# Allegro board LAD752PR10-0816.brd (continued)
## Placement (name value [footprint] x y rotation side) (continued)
CG220  1U_0402_6.3V4Z  [C_0402]  253.82 134.09 270 top
CG221  1U_0402_6.3V4Z  [C_0402]  250.82 134.12 270 top
CG222  1U_0402_6.3V6K  [C_0402]  265.79 102.86 0 bottom
CG223  1U_0402_6.3V6K  [C_0402]  265.85 125.47 0 bottom
CG224  1U_0402_6.3V6K  [C_0402]  266.7 105.53 180 bottom
CG225  1U_0402_6.3V6K  [C_0402]  266.76 122.74 180 bottom
CG226  1U_0402_6.3V6K  [C_0402]  272.59 129.16 270 bottom
CG227  1U_0402_6.3V6K  [C_0402]  277.44 100.95 270 top
CG228  1U_0402_6.3V6K  [C_0402]  275.39 128.25 90 bottom
CG229  1U_0402_6.3V6K  [C_0402]  276.54 100.9 180 top
CG230  10U_0603_6.3V6M  [C_0603]  281.76 114.9 270 top
CG231  1U_0402_6.3V4Z  [C_0402]  276.61 127.24 270 top
CG232  1U_0402_6.3V4Z  [C_0402]  271.58 128.25 90 bottom
CG233  1U_0402_6.3V4Z  [C_0402]  270.56 128.25 90 bottom
CG234  1U_0402_6.3V4Z  [C_0402]  283.84 119.35 0 bottom
CG235  0.1U_0402_10V6K  [C_0402]  283.84 120.81 0 bottom
CG236  0.1U_0402_10V6K  [C_0402]  279.79 115.04 270 top
CG237  0.1U_0402_10V6K  [C_0402]  284.02 124.51 90 bottom
CG238  0.1U_0402_10V6K  [C_0402]  280.36 126.32 90 top
CG239  0.1U_0402_10V6K  [C_0402]  277.75 114.14 0 top
CG240  0.1U_0402_10V6K  [C_0402]  277.75 115.03 0 top
CG241  0.1U_0402_10V6K  [C_0402]  283.84 117.76 0 bottom
CG242  0.1U_0402_10V6K  [C_0402]  277.59 126.39 0 top
CG243  1U_0402_6.3V4Z  [C_0402]  276.61 115.04 270 top
CG244  1U_0402_6.3V4Z  [C_0402]  280.68 115.04 270 top
CG245  1U_0402_6.3V4Z  [C_0402]  281.76 126.32 90 top
CG246  1U_0402_6.3V4Z  [C_0402]  283.84 102.08 0 bottom
CG247  10U_0603_6.3V6M  [C_0603]  281.89 107.16 180 top
CG248  1U_0402_6.3V4Z  [C_0402]  265.78 101.86 0 bottom
CG249  1U_0402_6.3V4Z  [C_0402]  281.11 112.24 0 top
CG250  1U_0402_6.3V4Z  [C_0402]  279.54 107.11 270 top
CG251  1U_0402_6.3V4Z  [C_0402]  283.84 104.62 0 bottom
CG252  0.1U_0402_10V6K  [C_0402]  281.57 101.07 270 top
CG253  0.1U_0402_10V6K  [C_0402]  280.64 105.72 0 top
CG254  0.1U_0402_10V6K  [C_0402]  279.78 105.02 180 top
CG255  0.1U_0402_10V6K  [C_0402]  277.3 109.82 0 top
CG256  0.1U_0402_10V6K  [C_0402]  283.84 101.12 0 bottom
CG257  0.1U_0402_10V6K  [C_0402]  277.41 112.77 0 top
CG258  0.1U_0402_10V6K  [C_0402]  283.84 103.35 0 bottom
CG259  0.1U_0402_10V6K  [C_0402]  279.33 112.24 0 top
CG260  1U_0402_6.3V4Z  [C_0402]  283.84 109.82 0 bottom
CG261  1U_0402_6.3V4Z  [C_0402]  277.3 103.35 0 top
CG262  1U_0402_6.3V4Z  [C_0402]  279.76 101.15 0 top
CG263  1U_0402_6.3V4Z  [C_0402]  279.78 108.32 180 top
CG264  1U_0402_6.3V6K  [C_0402]  265.79 91.94 0 bottom
CG265  1U_0402_6.3V6K  [C_0402]  265.79 74.82 0 bottom
CG266  1U_0402_6.3V6K  [C_0402]  266.7 94.61 180 bottom
CG267  1U_0402_6.3V6K  [C_0402]  266.7 77.49 180 bottom
CG268  1U_0402_6.3V6K  [C_0402]  283.84 95.47 0 bottom
CG269  1U_0402_6.3V6K  [C_0402]  278.57 72.61 180 top
CG270  1U_0402_6.3V6K  [C_0402]  283.84 99.24 0 bottom
CG271  1U_0402_6.3V6K  [C_0402]  276.79 72.61 180 top
CG272  10U_0603_6.3V6M  [C_0603]  276.3 91.92 180 top
CG273  1U_0402_6.3V4Z  [C_0402]  283.84 89.44 0 bottom
CG274  1U_0402_6.3V4Z  [C_0402]  283.84 90.84 0 bottom
CG275  1U_0402_6.3V4Z  [C_0402]  279.21 98.2 0 top
CG276  1U_0402_6.3V4Z  [C_0402]  283.84 87.09 0 bottom
CG277  0.1U_0402_10V6K  [C_0402]  283.84 94.14 0 bottom
CG278  0.1U_0402_10V6K  [C_0402]  278.25 93.38 0 top
CG279  0.1U_0402_10V6K  [C_0402]  280.98 98.2 0 top
CG280  0.1U_0402_10V6K  [C_0402]  283.84 97.44 0 bottom
CG281  0.1U_0402_10V6K  [C_0402]  283.84 91.73 0 bottom
CG282  0.1U_0402_10V6K  [C_0402]  278.15 91.85 180 top
CG283  0.1U_0402_10V6K  [C_0402]  277.26 86.97 225 top
CG284  0.1U_0402_10V6K  [C_0402]  279.99 91.85 180 top
CG285  1U_0402_6.3V4Z  [C_0402]  277.14 89.27 0 top
CG286  1U_0402_6.3V4Z  [C_0402]  276.55 95.17 270 top
CG287  1U_0402_6.3V4Z  [C_0402]  280.03 93.38 0 top
CG288  1U_0402_6.3V4Z  [C_0402]  283.84 88.55 0 bottom
CG289  10U_0603_6.3V6M  [C_0603]  283.85 77.44 0 bottom
CG290  1U_0402_6.3V4Z  [C_0402]  265.78 73.82 0 bottom
CG291  1U_0402_6.3V4Z  [C_0402]  270.47 71.09 180 bottom
CG292  1U_0402_6.3V4Z  [C_0402]  280.42 72.05 270 top
CG293  1U_0402_6.3V4Z  [C_0402]  283.84 74.26 0 bottom
CG294  0.1U_0402_10V6K  [C_0402]  272.92 71.09 0 bottom
CG295  0.1U_0402_10V6K  [C_0402]  283.84 75.66 0 bottom
CG296  0.1U_0402_10V6K  [C_0402]  283.84 73.31 0 bottom
CG297  0.1U_0402_10V6K  [C_0402]  277.26 75.24 0 top
CG298  0.1U_0402_10V6K  [C_0402]  283.84 81.57 0 bottom
CG299  0.1U_0402_10V6K  [C_0402]  283.84 84.17 0 bottom
CG300  0.1U_0402_10V6K  [C_0402]  280.41 71.09 0 bottom
CG301  0.1U_0402_10V6K  [C_0402]  283.84 82.9 0 bottom
CG302  1U_0402_6.3V4Z  [C_0402]  283.84 80.61 0 bottom
CG303  1U_0402_6.3V4Z  [C_0402]  282.9 83.08 270 top
CG304  1U_0402_6.3V4Z  [C_0402]  283.84 79.28 0 bottom
CG305  1U_0402_6.3V4Z  [C_0402]  278.51 71.09 0 bottom
CG306  0.1U_0402_10V7K  [C_0402]  206.38 88.36 0 bottom
CG3000  220U_D7_2VM_R6M  [C_EEFSS0D221R]  288.11 72.65 90 bottom
CH3  0.1U_0402_10V7K  [C_0402]  203.87 23.29 180 top
CH4  0.1U_0402_10V7K  [C_0402]  215.18 33.47 270 top
CH45  8.2P_0402_50V  [C_0402]  219.66 37.08 90 bottom
CH46  8.2P_0402_50V  [C_0402]  220.55 36.15 270 bottom
CH47  15P_0402_50V  [C_0402]  193.47 43.49 180 bottom
CH48  15P_0402_50V  [C_0402]  194.35 43.49 0 bottom
CH49  0.1U_0402_16V7K  [C_0402]  229.01 14.82 90 bottom
CH50  0.1U_0402_16V7K  [C_0402]  205.76 61.21 270 bottom
CH52  1U_0603_10V6K~D  [C_0603]  216.37 32.23 270 top
CH53  1U_0603_10V6K~D  [C_0603]  216.68 41.81 0 top
CH70  0.1U_0402_10V7K  [C_0402]  212.11 26.7 180 top
CH80  1U_0402_6.3V6K~D  [C_0402]  212.61 29.06 180 top
CH82  1U_0402_6.3V6K~D  [C_0402]  203.73 32.84 90 top
CH100  0.022U_0402_25V7K  [C_0402]  152.66 37.58 0 top
CH101  0.022U_0402_25V7K  [C_0402]  155.34 53.57 90 top
CH102  10U_0603_6.3V6M~D  [C_0603]  168.05 105.17 270 top
CH103  10U_0603_6.3V6M~D  [C_0603]  168.05 107.58 270 top
CH104  10U_0603_6.3V6M~D  [C_0603]  167.94 109.98 90 top
CH105  1U_0402_6.3V6K~D  [C_0402]  172.61 113.39 270 top
CH106  1U_0402_6.3V6K~D  [C_0402]  171.34 113.4 270 top
CH107  1U_0402_6.3V6K~D  [C_0402]  167.98 113.21 0 top
CH108  1U_0402_6.3V6K~D  [C_0402]  168.19 114.51 180 top
CH109  1U_0402_6.3V6K~D  [C_0402]  166.2 115.35 180 top
CH110  1U_0402_6.3V6K~D  [C_0402]  167.9 112.31 0 top
CH118  22U_0603_6.3V6M  [C_0603]  146.02 100.47 90 top
CH119  10U_0603_6.3V6M~D  [C_0603]  150.78 99.52 90 top
CH120  22U_0603_6.3V6M  [C_0603]  171.46 99.09 0 top
CH121  22U_0603_6.3V6M  [C_0603]  148.65 79.51 0 top
CH122  10U_0603_6.3V6M~D  [C_0603]  152.49 99.84 90 top
CH123  10U_0603_6.3V6M~D  [C_0603]  148.65 78.24 0 top
CH124  22U_0603_6.3V6M  [C_0603]  144.37 100.47 90 top
CH125  10U_0603_6.3V6M~D  [C_0603]  156.13 99.18 90 top
CH126  10U_0603_6.3V6M~D  [C_0603]  167.84 95.6 90 top
CH127  10U_0603_6.3V6M~D  [C_0603]  165.25 99.77 90 top
CH128  10U_0603_6.3V6M~D  [C_0603]  148.65 76.97 0 top
CH129  22U_0805_6.3V6M~D  [C_0805]  168.15 79.25 0 top
CH130  22U_0805_6.3V6M~D  [C_0805]  168.15 77.54 0 top
CH131  22U_0805_6.3V6M~D  [C_0805]  153.57 77.34 180 top
CH132  22U_0805_6.3V6M~D  [C_0805]  153.57 79.18 180 top
CH173  0.1U_0402_10V7K  [C_0402]  212.61 28.17 180 top
CH174  0.1U_0402_10V  [C_0402]  210.27 35.43 90 top
CH175  0.1U_0402_10V  [C_0402]  214.9 43.11 90 bottom
CH176  1U_0402_6.3V6K~D  [C_0402]  214.02 25.5 180 top
CH177  22U_0805_6.3V6M~D  [C_0805]  203.44 42.07 0 bottom
CH178  22U_0805_6.3V6M~D  [C_0805]  200.33 42.32 0 bottom
CH179  1U_0402_6.3V6K~D  [C_0402]  199.34 41.8 90 bottom
CH180  1U_0402_6.3V6K~D  [C_0402]  198.64 28.4 90 top
CH181  22U_0805_6.3V6M~D  [C_0805]  193.34 26 180 top
CH182  22U_0805_6.3V6M~D  [C_0805]  193.34 27.77 180 top
CH183  1U_0402_6.3V6K~D  [C_0402]  202.19 26.91 270 top
CH184  22U_0805_6.3V6M~D  [C_0805]  193.34 29.53 180 top
CH185  1U_0402_6.3V6K~D  [C_0402]  206.03 30.57 180 top
CH186  0.1U_0402_10V7K  [C_0402]  213.9 30.49 180 top
CH187  1U_0402_6.3V6K~D  [C_0402]  216.86 39.4 0 top
CH188  1U_0402_6.3V6K~D  [C_0402]  206.14 33.79 90 top
CH189  0.1U_0402_10V7K  [C_0402]  210.27 37.78 90 top
CH190  0.1U_0402_10V7K  [C_0402]  206.01 19.6 270 top
CH191  0.1U_0402_10V7K  [C_0402]  209.57 19.28 270 top
CH192  0.1U_0402_10V7K  [C_0402]  215.46 16.45 0 top
CH193  0.1U_0402_16V7K~D  [C_0402]  175 98.08 0 top
CH194  0.1U_0402_16V7K~D  [C_0402]  129.88 116.75 180 bottom
CH195  0.1U_0402_16V7K~D  [C_0402]  129.17 119.36 270 bottom
CH197  0.1U_0402_10V7K  [C_0402]  125.57 75.89 270 top
CH200  0.1U_0402_10V7K  [C_0402]  213 23.2 270 top
CH201  0.1U_0201_6.3V6K  [C_0201]  216.42 22.28 90 top
CH202  0.22U_0201_6.3V  [C_0201]  247.66 9.39 90 top
CH203  0.22U_0201_6.3V  [C_0201]  248.29 9.39 90 top
CH204  0.22U_0201_6.3V  [C_0201]  330.73 36.23 180 top
CH205  0.22U_0201_6.3V  [C_0201]  330.73 35.59 180 top
CH206  0.22U_0201_6.3V  [C_0201]  330.75 37.57 180 top
CH207  0.22U_0201_6.3V  [C_0201]  330.75 36.94 180 top
CH208  0.22U_0201_6.3V  [C_0201]  250.83 9.39 90 top
CH209  0.22U_0201_6.3V  [C_0201]  251.47 9.39 90 top
CH210  0.22U_0201_6.3V  [C_0201]  239.18 10.19 180 top
CH211  0.22U_0201_6.3V  [C_0201]  239.18 9.56 180 top
CH212  0.22U_0201_6.3V  [C_0201]  243.21 9.77 180 top
CH213  0.22U_0201_6.3V  [C_0201]  243.21 9.14 180 top
CH214  0.22U_0201_6.3V  [C_0201]  269.57 12.3 180 bottom
CH215  0.22U_0201_6.3V  [C_0201]  269.57 11.65 180 bottom
CH216  0.22U_0201_6.3V  [C_0201]  269.77 15.72 180 bottom
CH217  0.22U_0201_6.3V  [C_0201]  269.77 15.08 180 bottom
CH218  0.22U_0201_6.3V  [C_0201]  269.07 21.04 0 bottom
CH219  0.22U_0201_6.3V  [C_0201]  269.07 21.67 0 bottom
CH220  0.22U_0201_6.3V  [C_0201]  268.4 17.6 0 bottom
CH221  0.22U_0201_6.3V  [C_0201]  268.4 18.23 0 bottom
CI38  0.1U_0402_10V6K  [C_0402]  165.68 173.77 90 bottom
CI39  0.1U_0402_10V6K  [C_0402]  166.57 173.77 90 bottom
CL1  0.1U_0402_16V7K  [C_0402]  234.06 149.5 270 bottom
CL2  0.1U_0402_16V7K  [C_0402]  234.95 149.5 270 bottom
CL3  0.1U_0402_16V7K  [C_0402]  231.59 152.91 180 bottom
CL4  0.1U_0402_16V7K  [C_0402]  231.59 153.8 180 bottom
CL5  1U_0402_6.3V6K~D  [C_0402]  237.3 156.42 270 top
CL6  0.1U_0402_16V7K~D  [C_0402]  238.19 156.42 270 top
CL7  0.1U_0402_16V7K~D  [C_0402]  237.49 149.5 270 bottom
CL8  18P_0402_50V8J  [C_0402]  238.64 157.97 180 bottom
CL9  22P_0402_50V8J  [C_0402]  235.89 157.97 0 bottom
CL11  1000P_0402_50V7K~D  [C_0402]  232.72 157.79 90 bottom
CL12  0.1U_0402_16V7K~D  [C_0402]  229.31 150.9 90 bottom
CL13  1U_0402_6.3V6K~D  [C_0402]  230.2 150.9 90 bottom
CL14  10U_0603_6.3V6M~D  [C_0603]  230.51 149.64 270 bottom
CL15  10U_0603_6.3V6M~D  [C_0603]  229.24 149.64 270 bottom
CL16  0.1U_0402_16V7K~D  [C_0402]  238.2 151.86 270 top
CL17  1U_0402_6.3V6K~D  [C_0402]  238.26 152.75 180 top
CL18  1U_0402_6.3V6K~D  [C_0402]  236.41 156.42 270 top
CL19  0.1U_0402_16V7K~D  [C_0402]  235.52 156.42 270 top
CL20  0.1U_0402_16V7K~D  [C_0402]  233.42 152.75 0 top
CL21  1U_0402_6.3V6K~D  [C_0402]  233.41 151.33 0 top
CL22  4.7U_0603_6.3V6K~D  [C_0603]  231.9 152.85 180 top
CL23  0.1U_0402_16V7K~D  [C_0402]  233.41 150.44 0 top
CL24  0.1U_0402_16V7K~D  [C_0402]  238.26 154.15 180 top
CL25  0.1U_0402_16V7K~D  [C_0402]  239.98 151.23 180 top
CL27  470P_0402_50V7K  [C_0402]  241.82 165.78 270 top
CL28  470P_0402_50V7K  [C_0402]  258.52 166.67 270 top
CL29  470P_0402_50V7K  [C_0402]  259.41 166.67 270 top
CL30  10P_1808_3KV7K~D  [C_1808]  254.83 166.29 270 bottom
CL31  470P_0402_50V7K  [C_0402]  260.74 166.67 270 top
CL32  1000P_0402_50V7K~D  [C_0402]  242.85 159.67 180 top
CL33  0.1U_0402_16V7K~D  [C_0402]  241.93 162.59 0 top
CL34  1000P_0402_50V7K~D  [C_0402]  242.85 163.48 180 top
CL35  0.1U_0402_16V7K~D  [C_0402]  241.93 160.56 0 top
CL36  1000P_0402_50V7K~D  [C_0402]  242.85 155.54 180 top
CL37  0.1U_0402_16V7K~D  [C_0402]  241.93 154.65 0 top
CL38  1000P_0402_50V7K~D  [C_0402]  242.85 153.07 180 top
CL39  0.1U_0402_16V7K~D  [C_0402]  241.93 152.18 0 top
CL40  4.7U_0805_10V4Z  [C_0805]  224.38 148.56 180 bottom
CL41  0.1U_0402_16V7K  [C_0402]  224.29 149.87 180 bottom
CL42  0.1U_0402_16V7K  [C_0402]  226.37 146.23 90 bottom
CL43  1U_0402_6.3V6K~D  [C_0402]  233.36 155.45 0 top
CL44  0.1U_0402_16V7K~D  [C_0402]  233.36 154.21 0 top
CLRP1  SHORT PADS  [SHORTPADS]  175.08 32.54 270 bottom
CM9  0.1U_0402_10V7K  [C_0402]  134.11 160.39 90 bottom
CM10  0.1U_0402_10V7K  [C_0402]  302.88 40.74 90 top
CM11  4.7U_0805_10V4Z  [C_0805]  311.07 42.32 0 top
CM12  22U_0603_6.3V6M~D  [C_0603]  301.8 40.75 90 top
CM13  0.1U_0402_10V7K~D  [C_0402]  300.72 40.74 90 top
CM14  22U_0603_6.3V6M~D  [C_0603]  315.6 40.29 90 top
CM15  0.1U_0402_10V7K~D  [C_0402]  317.23 40.74 90 top
CM16  0.1U_0402_10V7K  [C_0402]  172.4 159.42 0 bottom
CM17  0.1U_0402_10V7K  [C_0402]  172.4 160.31 0 bottom
CM18  0.1U_0402_10V7K  [C_0402]  168.41 161.37 90 bottom
CM19  22U_0603_6.3V6M  [C_0603]  164.16 160.5 270 bottom
CM20  0.1U_0402_10V7K  [C_0402]  168.34 152.36 270 bottom
CM21  1U_0402_6.3V  [C_0402]  165.99 152.36 270 bottom
CM23  0.1U_0402_10V7K  [C_0402]  162.25 174.49 270 bottom
CM29  10U_0603_6.3V6M  [C_0603]  126.69 152.43 0 top
CM30  1U_0402_6.3V  [C_0402]  125.23 155.2 180 bottom
CM31  10U_0603_6.3V6M  [C_0603]  126.69 153.64 0 top
CM32  0.1U_0402_10V7K  [C_0402]  131.12 151.47 270 bottom
CM33  1U_0402_6.3V  [C_0402]  125.23 156.09 180 bottom
CM34  0.1U_0402_10V7K  [C_0402]  138.43 155.54 0 bottom
CM35  0.1U_0402_10V7K  [C_0402]  129.6 151.47 270 bottom
CM36  0.1U_0402_10V7K  [C_0402]  130.74 160.39 90 bottom
CM62  0.22U_0201_6.3V  [C_0201]  133.22 148.65 90 bottom
CM63  0.22U_0201_6.3V  [C_0201]  132.97 150.55 90 bottom
CM64  0.22U_0201_6.3V  [C_0201]  136.9 148.65 90 bottom
CM65  0.22U_0201_6.3V  [C_0201]  136.01 148.65 90 bottom
CM66  0.22U_0201_6.3V  [C_0201]  132.08 150.55 90 bottom
CM67  0.22U_0201_6.3V  [C_0201]  135.57 150.55 90 bottom
CM68  0.22U_0201_6.3V  [C_0201]  134.11 148.65 90 bottom
CM69  0.22U_0201_6.3V  [C_0201]  134.68 150.55 90 bottom
CM70  0.1U_0402_10V7K  [C_0402]  149.61 170.92 270 bottom
CM98  0.01U_0402_16V7K  [C_0402]  163.28 163.04 180 bottom
CM99  0.01U_0402_16V7K  [C_0402]  163.28 161.7 180 bottom
CN9  1U_0402_10V6K  [C_0402]  314.33 41.87 90 top
CN23  0.1U_0402_16V7K  [C_0402]  307.13 38.07 90 top
CN24  0.1U_0402_16V7K  [C_0402]  308.02 38.07 90 top
CN25  1U_0402_10V6K  [C_0402]  316.04 37.23 180 top
CPU1  SKL-H_BGA1440  [SKL-H_BGA_1440P-T]  172.98 93.59 270 bottom
CS1  10U_0603_25V6M  [C_0603]  127.45 10.13 270 top
CS2  10U_0603_6.3V6M  [C_0603]  179.9 68.08 90 top
CS5  1000P_0402_50V7K~D  [C_0402]  125.48 10.14 270 top
CS6  0.1U_0402_25V6K~D  [C_0402]  126.37 10.14 270 top
CS7  0.1U_0402_16V4Z  [C_0402]  180.3 71.09 180 top
CS16  22U_0402_6.3V6M  [C_0402]  126.37 11.72 90 top
CT1  0.22U_0201_6.3V  [C_0201]  188.35 162.61 180 top
CT2  0.22U_0201_6.3V  [C_0201]  188.35 163.18 180 top
CT3  0.22U_0201_6.3V  [C_0201]  188.35 160.32 180 top
CT4  0.22U_0201_6.3V  [C_0201]  188.35 164.32 180 top
CT5  0.22U_0201_6.3V  [C_0201]  188.35 166.61 180 top
CT6  0.1U_0201_6.3V6K  [C_0201]  177.42 157.43 90 top
CT7  0.1U_0201_6.3V6K  [C_0201]  177.99 157.43 90 top
CT8  0.1U_0201_6.3V6K  [C_0201]  179.14 157.43 90 top
CT9  0.1U_0201_6.3V6K  [C_0201]  178.57 157.43 90 top
CT10  0.1U_0201_6.3V6K  [C_0201]  180.28 157.43 90 top
CT11  0.1U_0201_6.3V6K  [C_0201]  181.42 157.43 90 top
CT12  0.22U_0201_6.3V  [C_0201]  188.35 163.75 180 top
CT13  0.22U_0201_6.3V  [C_0201]  188.35 162.04 180 top
CT14  0.22U_0201_6.3V  [C_0201]  188.35 161.47 180 top
CT15  0.22U_0201_6.3V  [C_0201]  188.35 159.75 180 top
CT16  0.22U_0201_6.3V  [C_0201]  188.35 160.89 180 top
CT18  0.22U_0201_6.3V  [C_0201]  188.35 164.9 180 top
CT21  0.22U_0201_6.3V  [C_0201]  188.35 167.18 180 top
CT23  0.1U_0201_6.3V6K  [C_0201]  179.71 157.43 90 top
CT24  0.1U_0201_6.3V6K  [C_0201]  180.85 157.43 90 top
CT25  0.1U_0201_6.3V6K  [C_0201]  179.39 152.69 90 bottom
CT26  0.1U_0201_6.3V6K  [C_0201]  178.82 152.69 90 bottom
CT27  0.1U_0201_6.3V6K  [C_0201]  182.57 157.43 90 top
CT28  0.1U_0201_6.3V6K  [C_0201]  182 157.43 90 top
CT29  0.1U_0201_6.3V6K  [C_0201]  183.71 157.43 90 top
CT30  0.1U_0201_6.3V6K  [C_0201]  183.14 157.43 90 top
CT31  0.1U_0201_6.3V6K  [C_0201]  184.85 157.43 90 top
CT32  0.1U_0201_6.3V6K  [C_0201]  184.28 157.43 90 top
CT33  0.1U_0201_6.3V6K  [C_0201]  186 157.43 90 top
CT34  0.1U_0201_6.3V6K  [C_0201]  185.42 157.43 90 top
CT35  0.1U_0201_6.3V6K  [C_0201]  181.35 152.69 90 bottom
CT36  0.1U_0201_6.3V6K  [C_0201]  181.95 152.68 90 bottom
CT37  12P_0402_50V8J  [C_0402]  190.84 170.34 180 top
CT38  12P_0402_50V8J  [C_0402]  190.52 168.82 180 top
CT39  0.22U_0201_6.3V  [C_0201]  183.15 172.68 270 top
CT40  0.22U_0201_6.3V  [C_0201]  182.58 172.68 270 top
CT41  0.22U_0201_6.3V  [C_0201]  184.04 172.68 270 top
CT42  0.22U_0201_6.3V  [C_0201]  184.61 172.68 270 top
CT43  0.1U_0201_6.3V6K  [C_0201]  182.62 159.67 90 bottom
CT44  0.1U_0201_6.3V6K  [C_0201]  182.05 159.67 90 bottom
CT45  0.1U_0201_6.3V6K  [C_0201]  188.67 154.41 270 bottom
CT46  0.1U_0201_6.3V6K  [C_0201]  178.75 162.54 270 bottom
CT47  1U_0201_6.3V6M  [C_0201]  178.11 167.68 270 bottom
CT48  1U_0201_6.3V6M  [C_0201]  181.9 163.74 0 bottom
CT49  1U_0201_6.3V6M  [C_0201]  176.43 171.61 180 top
CT50  10U_0402_6.3V6M  [C_0402]  176.87 172.37 180 top
CT51  10U_0402_6.3V6M  [C_0402]  176.87 173.26 180 top
CT52  10U_0402_6.3V6M  [C_0402]  176.87 174.15 180 top
CT53  10U_0402_6.3V6M  [C_0402]  177.73 174.31 0 top
CT54  1U_0201_6.3V6M  [C_0201]  179.38 162.54 270 bottom
CT55  1U_0201_6.3V6M  [C_0201]  184.57 163.8 0 bottom
CT56  1U_0201_6.3V6M  [C_0201]  187.18 158.05 180 top
CT57  1U_0201_6.3V6M  [C_0201]  175.45 153.02 270 bottom
CT58  1U_0201_6.3V6M  [C_0201]  176.08 153.02 270 bottom
CT59  1U_0201_6.3V6M  [C_0201]  181.29 165.21 270 bottom
CT60  1U_0201_6.3V6M  [C_0201]  181.86 162.48 270 bottom
CT61  1U_0201_6.3V6M  [C_0201]  179.38 165.02 270 bottom
CT62  1U_0201_6.3V6M  [C_0201]  178.6 165.68 180 bottom
CT63  1U_0201_6.3V6M  [C_0201]  179.4 168.6 270 bottom
CT64  1U_0201_6.3V6M  [C_0201]  180.41 169.22 90 bottom
CT65  1U_0201_6.3V6M  [C_0201]  179.84 169.22 90 bottom
CT66  1U_0201_6.3V6M  [C_0201]  180.98 169.22 90 bottom
CT67  1U_0201_6.3V6M  [C_0201]  179.24 169.81 180 bottom
CT68  1U_0201_6.3V6M  [C_0201]  179.24 169.23 180 bottom
CT69  1U_0201_6.3V6M  [C_0201]  181.56 169.22 90 bottom
CT70  1U_0201_6.3V6M  [C_0201]  187.77 159 0 top
CT71  1U_0201_6.3V6M  [C_0201]  183.93 164.43 0 bottom
CT72  1U_0201_6.3V6M  [C_0201]  183.12 164.43 180 bottom
CT73  47U_0603_6.3V6M  [C_0603]  172.96 172.26 90 bottom
CT74  47U_0603_6.3V6M  [C_0603]  171.62 172.26 90 bottom
CT75  47U_0603_6.3V6M  [C_0603]  170.29 172.26 90 bottom
CT77  1U_0201_6.3V6M  [C_0201]  183.17 162.57 0 bottom
CT78  1U_0201_6.3V6M  [C_0201]  174.81 153.02 270 bottom
CT79  1U_0201_6.3V6M  [C_0201]  181.29 163.42 90 bottom
CT80  1U_0201_6.3V6M  [C_0201]  180.08 163.8 90 bottom
CT81  10U_0402_6.3V6M  [C_0402]  183.54 168.8 90 bottom
CT82  10U_0402_6.3V6M  [C_0402]  182.65 168.8 90 bottom
CT83  1U_0201_6.3V6M  [C_0201]  181.15 167.16 180 bottom
CT84  1U_0201_6.3V6M  [C_0201]  183.42 166.97 0 bottom
CT85  1U_0201_6.3V6M  [C_0201]  183.97 166.25 270 bottom
CT86  1U_0201_6.3V6M  [C_0201]  182.63 166.33 90 bottom
CT88  0.1U_0402_10V6K  [C_0402]  195.6 163.67 180 top
CT90  22U_0603_6.3V6M  [C_0603]  203.83 158.31 180 bottom
CT91  22U_0603_6.3V6M  [C_0603]  205.02 158.92 270 bottom
CT92  22U_0603_6.3V6M  [C_0603]  204.72 160.15 0 bottom
CT93  22U_0603_6.3V6M  [C_0603]  204.72 161.36 0 bottom
CT94  0.47U_0402_25V6K  [C_0402]  194.9 179.72 180 top
CT95  0.47U_0402_25V6K  [C_0402]  190.31 177.95 0 top
CT96  0.47U_0402_25V6K  [C_0402]  193.18 177.62 0 top
CT97  0.47U_0402_25V6K  [C_0402]  191.28 179.59 180 top
CT98  2.2U_0603_16V6K  [C_0603]  195.97 161.26 180 bottom
CT99  4.7U_0603_10V6K  [C_0603]  197.56 158.02 180 bottom
CT100  4.7U_0603_10V6K  [C_0603]  198.26 165.13 90 top
CT101  1U_0402_6.3V6K  [C_0402]  197.1 164.18 0 top
CT102  1U_0201_6.3V6M  [C_0201]  196.22 167.47 90 top
CT103  10U_0402_6.3V6M  [C_0402]  195.6 162.34 180 bottom
CT104  0.22U_0402_10V4Z  [C_0402]  202.63 167.19 90 bottom
CT106  1U_0603_25V6K  [C_0603]  204.61 160.94 180 top
CT108  0.22U_0201_6.3V  [C_0201]  188.35 166.04 180 top
CT109  0.22U_0201_6.3V  [C_0201]  188.35 165.47 180 top
CT110  0.22U_0201_6.3V  [C_0201]  188.35 167.75 180 top
CT111  0.22U_0201_6.3V  [C_0201]  188.35 168.32 180 top
CT112  220P_0201_25V7K  [C_0201]  202.95 165.78 270 top
CT113  220P_0201_25V7K  [C_0201]  203.73 166.38 270 top
CU2  47U_0805_6.3V6M  [C_0805]  19.92 43.59 0 bottom
CU3  10U_0603_6.3V6M~D  [C_0603]  20.07 42.13 0 bottom
CU6  150U_B15G_6.3VM_R70M  [C_B15G]  20.35 46.26 0 bottom
CU7  0.1U_0402_16V7K  [C_0402]  20.38 41.6 180 top
CU10  47U_0805_6.3V6M  [C_0805]  265.86 21.74 180 bottom
CU11  10U_0603_6.3V6M~D  [C_0603]  265.89 23.79 90 bottom
CU12  0.1U_0402_10V7K  [C_0402]  24.16 39.69 0 top
CU13  0.1U_0402_10V7K  [C_0402]  24.16 38.8 0 top
CU16  0.1U_0402_16V7K  [C_0402]  261.18 25.23 90 bottom
CU17  0.1U_0402_16V7K  [C_0402]  261.18 24.3 270 bottom
CU18  0.47U_0402_25V6K  [C_0402]  9.57 61.37 0 top
CU19  0.47U_0402_25V6K  [C_0402]  11.95 57.31 0 bottom
CU20  0.47U_0402_25V6K  [C_0402]  11.06 62.26 270 bottom
CU21  0.47U_0402_25V6K  [C_0402]  11.06 57.83 270 bottom
CU26  0.1U_0402_16V7K  [C_0402]  27.92 42.74 0 top
CU27  2.2U_0603_6.3V6K  [C_0603]  31.68 44.2 90 top
CU28  0.1U_0402_16V7K  [C_0402]  32.81 47.14 180 top
CU29  0.1U_0402_16V7K  [C_0402]  29.7 46.23 0 top
CU30  0.1U_0402_10V7K  [C_0402]  14.63 61.93 0 top
CU31  0.1U_0402_10V7K  [C_0402]  14.63 62.88 0 top
CU32  2.2U_0603_25V6K  [C_0603]  14.5 54.16 90 bottom
CU33  47U_0603_6.3V6M  [C_0603]  22.63 53.5 90 bottom
CU34  0.1U_0402_16V7K  [C_0402]  21.23 53.76 90 bottom
CU35  0.1U_0402_16V7K  [C_0402]  20.77 50.65 270 bottom
CU37  10U_0805_25V6K  [C_0805]  12.91 54.26 90 bottom
CU38  0.1U_0402_10V7K  [C_0402]  14.74 58.47 0 top
CU39  0.1U_0402_10V7K  [C_0402]  14.74 57.58 0 top
CU40  150U_B15G_6.3VM_R70M  [C_B15G]  13.27 52 270 bottom
CU42  47U_0603_6.3V6M  [C_0603]  21.73 50.2 0 bottom
CU44  47U_0603_6.3V6M  [C_0603]  21.28 52.99 90 top
CU45  0.1U_0402_10V7K  [C_0402]  267.52 24.28 90 bottom
CU46  0.1U_0402_10V7K  [C_0402]  263.19 27.82 90 bottom
CU47  0.1U_0402_10V7K  [C_0402]  18.65 48.11 180 top
CU48  10U_0402_6.3V6M  [C_0402]  264.14 27.82 90 bottom
CV1  0.1U_0201_6.3V6K  [C_0201]  147.07 167.27 270 top
CV2  0.1U_0201_6.3V6K  [C_0201]  147.71 167.27 270 top
CV3  0.1U_0201_6.3V6K  [C_0201]  148.41 167.58 270 top
CV4  0.1U_0201_6.3V6K  [C_0201]  149.04 167.58 270 top
CV5  4.7U_0805_10V4Z  [C_0805]  161.93 165.04 90 bottom
CV6  0.1U_0201_6.3V6K  [C_0201]  150.31 167.58 270 top
CV7  0.1U_0201_6.3V6K  [C_0201]  150.57 166.19 270 top
CV8  0.1U_0201_6.3V6K  [C_0201]  149.68 167.58 270 top
CV9  0.1U_0402_10V7K  [C_0402]  165.41 170.21 0 bottom
CV10  4.7U_0805_10V4Z  [C_0805]  163.48 169.58 180 bottom
CV11  0.1U_0201_6.3V6K  [C_0201]  151.2 166.19 270 top
CV12  0.1U_0201_6.3V6K  [C_0201]  151.58 167.58 270 top
CV13  0.1U_0201_6.3V6K  [C_0201]  152.15 167.58 270 top
CV14  0.1U_0603_25V7K  [C_0603]  172.6 182.28 0 top
CV15  1000P_0402_50V7K  [C_0402]  159.75 167.48 0 bottom
CV17  0.1U_0402_10V7K  [C_0402]  165.41 169.26 0 bottom
CV18  10U_0603_6.3V6M  [C_0603]  163.08 168.05 180 bottom
CV19  0.1U_0402_10V7K  [C_0402]  168.56 170.88 180 bottom
CV20  0.1U_0402_16V7K  [C_0402]  225.52 165.41 180 bottom
CV21  4.7U_0805_10V4Z  [C_0805]  168.09 168.97 270 bottom
CV22  1000P_0402_50V7K  [C_0402]  211.07 107.03 0 bottom
CV23  0.1U_0201_6.3V6K  [C_0201]  232.71 163.9 0 bottom
CV24  0.1U_0201_6.3V6K  [C_0201]  228.17 155.2 180 bottom
CV25  0.1U_0201_6.3V6K  [C_0201]  228.17 156.09 180 bottom
CV26  0.1U_0201_6.3V6K  [C_0201]  230.28 166.68 90 bottom
CV27  0.1U_0201_6.3V6K  [C_0201]  229.33 166.68 90 bottom
CV28  0.1U_0201_6.3V6K  [C_0201]  241.48 167.51 90 top
CV29  0.1U_0201_6.3V6K  [C_0201]  234.56 166.68 90 bottom
CV30  0.1U_0201_6.3V6K  [C_0201]  242.37 167.51 90 top
CV31  0.1U_0201_6.3V6K  [C_0201]  235.51 166.68 90 bottom
CV32  0.1U_0201_6.3V6K  [C_0201]  241.65 166.68 90 bottom
CV33  0.1U_0201_6.3V6K  [C_0201]  240.76 166.68 90 bottom
CV34  10U_0402_6.3V6M  [C_0402]  238.93 166.68 180 bottom
CV35  0.1U_0201_6.3V6K  [C_0201]  238.45 167.67 180 bottom
CV36  0.1U_0402_10V  [C_0402]  231.66 147.78 270 bottom
CV37  0.1U_0402_10V  [C_0402]  227.09 147.76 225 top
CV67  1U_0402_16V6K  [C_0402]  216.72 151.58 270 bottom
CV372  10P_0402_50V8J  [C_0402]  162.39 163.93 180 bottom
CV373  10P_0402_50V8J  [C_0402]  165.41 168.31 0 bottom
CV374  10P_0402_50V8J  [C_0402]  165.8 162.66 315 top
CV375  10P_0402_50V8J  [C_0402]  170.14 182.1 180 top
CV416  0.1U_0201_6.3V6K  [C_0201]  181.95 111.18 180 bottom
CV417  0.1U_0201_6.3V6K  [C_0201]  181.95 112.13 180 bottom
CV418  0.1U_0201_6.3V6K  [C_0201]  183.28 112.38 180 bottom
CV419  0.1U_0201_6.3V6K  [C_0201]  183.28 113.34 180 bottom
CV420  0.1U_0201_6.3V6K  [C_0201]  181.31 113.59 180 bottom
CV421  0.1U_0201_6.3V6K  [C_0201]  181.31 114.54 180 bottom
CV422  0.1U_0201_6.3V6K  [C_0201]  183.28 114.92 180 bottom
CV423  0.1U_0201_6.3V6K  [C_0201]  183.28 115.88 180 bottom
CV424  0.1U_0201_6.3V6K  [C_0201]  187.89 122.61 90 bottom
CV425  0.1U_0201_6.3V6K  [C_0201]  186.94 122.61 90 bottom
CV426  0.1U_0201_6.3V6K  [C_0201]  181.31 116.26 180 bottom
CV427  0.1U_0201_6.3V6K  [C_0201]  181.31 117.21 180 bottom
CV428  0.1U_0201_6.3V6K  [C_0201]  183.28 117.53 180 bottom
CV429  0.1U_0201_6.3V6K  [C_0201]  183.28 118.48 180 bottom
CV430  0.1U_0201_6.3V6K  [C_0201]  181.31 118.8 180 bottom
CV431  0.1U_0201_6.3V6K  [C_0201]  181.31 119.75 180 bottom
CV432  0.1U_0201_6.3V6K  [C_0201]  183.28 120.07 180 bottom
CV433  0.1U_0201_6.3V6K  [C_0201]  183.28 121.02 180 bottom
CV434  0.1U_0201_6.3V6K  [C_0201]  189.8 122.61 90 bottom
CV435  0.1U_0201_6.3V6K  [C_0201]  188.85 122.61 90 bottom
CV436  0.1U_0402_16V4Z  [C_0402]  185.76 121.96 180 bottom
CV437  0.1U_0402_16V4Z  [C_0402]  183.07 109.61 270 bottom
CV438  2.2U_0402_6.3V6M  [C_0402]  191.5 113.16 0 bottom
CV439  1U_0402_6.3V6K  [C_0402]  192.4 110.42 90 bottom
CV440  0.1U_0402_10V7K  [C_0402]  221.17 161.2 90 bottom
CV441  0.1U_0402_10V7K  [C_0402]  220.8 151.59 270 bottom
CV442  0.01U_0402_16V7K  [C_0402]  219.9 151.59 270 bottom
CV443  0.01U_0402_16V7K  [C_0402]  213.66 158.39 180 bottom
CV444  0.01U_0402_16V7K  [C_0402]  213.65 156.19 180 bottom
CV445  0.01U_0402_16V7K  [C_0402]  224.01 154.17 270 bottom
CV446  0.01U_0402_16V7K  [C_0402]  213.74 152.76 180 bottom
CV447  0.1U_0402_10V7K  [C_0402]  223.11 154.17 270 bottom
CV484  0.1U_0402_16V4Z  [C_0402]  197.87 88.79 90 bottom
CV651  1U_0402_6.3V4Z  [C_0402]  213.62 109.68 90 bottom
CV1056  0.1U_0402_16V7K  [C_0402]  208.66 158.51 270 bottom
CV1057  0.1U_0201_6.3V6K  [C_0201]  213.61 160.22 180 bottom
CV1058  0.1U_0201_6.3V6K  [C_0201]  213.61 159.59 180 bottom
CV1059  0.1U_0201_6.3V6K  [C_0201]  213.62 157.03 180 bottom
CV1060  0.1U_0201_6.3V6K  [C_0201]  213.62 157.65 180 bottom
CV1061  0.1U_0201_6.3V6K  [C_0201]  213.62 154.86 180 bottom
CV1062  0.1U_0201_6.3V6K  [C_0201]  213.63 155.48 180 bottom
CV1063  0.1U_0201_6.3V6K  [C_0201]  213.66 153.5 180 bottom
CV1064  0.1U_0201_6.3V6K  [C_0201]  213.66 154.11 180 bottom
CV1068  10U_0603_6.3V6M~D  [C_0603]  222.13 169.2 0 bottom
CV1069  0.1U_0201_6.3V6K  [C_0201]  222.35 170.12 0 bottom
CV1312  1U_0603_6.3V6M  [C_0603]  212.56 148.98 270 bottom
CV1313  10U_0603_6.3V6M  [C_0603]  219.71 148.91 270 bottom
CV1314  10U_0603_6.3V6M  [C_0603]  214.05 150.16 180 bottom
CX1  0.1U_0402_16V7K  [C_0402]  232.21 167.6 270 bottom
CX2  0.1U_0402_16V7K  [C_0402]  213.57 161.04 90 bottom
DA1  -  [BAT54C-7-F_SOT23-3]  38.35 25.43 270 top
DA2  BAT54AW_SOT323-3~D  [BAT54AW_SOT323-3]  36.86 22.57 90 bottom
DA3  BAT54AW_SOT323-3~D  [BAT54AW_SOT323-3]  35.14 41.4 180 top
DA4  AZ5125-02S.R7G_SOT23-3  [AZ5125-02SPR7G_SOT23-3]  22.45 18.19 270 bottom
DA5  AZ5123-02S SOT23  [AZ5125-02SPR7G_SOT23-3]  22.45 18.19 90 top
DA6  AZ5125-02S.R7G_SOT23-3  [AZ5125-02SPR7G_SOT23-3]  21.03 33.08 0 bottom
DA7  AZ5125-02S.R7G_SOT23-3  [AZ5125-02SPR7G_SOT23-3]  48.77 11.54 90 top
DA8  AZ5125-02S.R7G_SOT23-3  [AZ5125-02SPR7G_SOT23-3]  48.77 7.54 90 top
DE1  SDMK0340L-7-F_SOD323-2~D  [SDMK0340L-7-F_SOD323-2]  313.2 22.07 0 top
DE2  -  [RB751V-40_SOD323-2]  221.64 44.18 270 bottom
DE3  -  [RB751V-40_SOD323-2]  223.36 44.18 270 bottom
DE4  -  [RB751V-40_SOD323-2]  219.97 44.18 270 bottom
DF1  -  [SDMK0340L-7-F_SOD323-2]  103.7 60.03 270 top
DF2  -  [SDMK0340L-7-F_SOD323-2]  291.02 72.1 0 top
DG1  -  [SDMK0340L-7-F_SOD323-2]  204.08 91.87 180 bottom
DH1  -  [RB751V-40_SOD323-2]  223.78 27.27 90 bottom
DS1  SDM10U45-7_SOD523-2~D  [SDM10U45-7_SOD523-2]  186.7 69.76 0 top
DT1  SDM10U45-7_SOD523-2~D  [SDM10U45-7_SOD523-2]  190.74 175.7 90 top
DT2  ESD8011MUT5G X3DFN2 ESD  [ESD108-B1-CSP0201_WLL-2-1-2]  190.12 175.84 180 bottom
DT3  ESD8011MUT5G X3DFN2 ESD  [ESD108-B1-CSP0201_WLL-2-1-2]  190.78 175.84 0 bottom
DT4  ESD8011MUT5G X3DFN2 ESD  [ESD108-B1-CSP0201_WLL-2-1-2]  187.21 174.53 180 bottom
DT5  ESD8011MUT5G X3DFN2 ESD  [ESD108-B1-CSP0201_WLL-2-1-2]  187.91 174.53 0 bottom
DT6  ESD8011MUT5G X3DFN2 ESD  [ESD108-B1-CSP0201_WLL-2-1-2]  196.27 174.12 0 top
DT7  ESD8011MUT5G X3DFN2 ESD  [ESD108-B1-CSP0201_WLL-2-1-2]  195.61 174.12 180 top
DT8  ESD8011MUT5G X3DFN2 ESD  [ESD108-B1-CSP0201_WLL-2-1-2]  196.31 174.12 0 bottom
DT9  ESD8011MUT5G X3DFN2 ESD  [ESD108-B1-CSP0201_WLL-2-1-2]  195.61 174.12 180 bottom
DT10  -  [TVWDF1004AD0_DFN9]  191.81 174.37 0 bottom
DT11  ESD8011MUT5G X3DFN2 ESD  [ESD108-B1-CSP0201_WLL-2-1-2]  191.27 173.77 0 top
DT12  ESD8011MUT5G X3DFN2 ESD  [ESD108-B1-CSP0201_WLL-2-1-2]  196.9 175.89 90 top
DT13  ESD8011MUT5G X3DFN2 ESD  [ESD108-B1-CSP0201_WLL-2-1-2]  194.8 175.86 90 top
DT14  ESD8011MUT5G X3DFN2 ESD  [ESD108-B1-CSP0201_WLL-2-1-2]  188.54 176.12 180 top
DT15  AZ4024-02S_SOT23-3~D  [PESD24VS2UT_SOT23-3]  207.53 167.33 0 bottom
DU1  -  [L30ESDL5V0C3-2_SOT23-3]  20.37 36.99 90 bottom
DU2  -  [TVWDF1004AD0_DFN9]  20.23 37.49 90 top
DU6  -  [SDMK0340L-7-F_SOD323-2]  31.88 48.52 0 top
DU8  -  [SDMK0340L-7-F_SOD323-2]  34.16 46.29 270 top
DU11  -  [L30ESDL5V0C3-2_SOT23-3]  11.86 59.72 90 bottom
DU12  -  [TVWDF1004AD0_DFN9]  10.71 62.39 90 top
DU13  -  [TVWDF1004AD0_DFN9]  9.77 59.76 270 top
DU20  AZC199-02SPR7G_SOT23-3  [PSOT24C_SOT23-3]  15.12 63.79 270 bottom
DU21  AZC199-02SPR7G_SOT23-3  [PSOT24C_SOT23-3]  14.32 67.79 270 bottom
DV1  -  [RB751V-40_SOD323-2]  168.74 159.39 0 top
DV2  -  [PESD5V0U2BT_SOT23-3]  162.7 164.54 0 top
DV4  AZC199-02SPR7G_SOT23-3  [PSOT24C_SOT23-3]  166.63 164.54 0 top
DV14  AZC199-02SPR7G_SOT23-3  [PSOT24C_SOT23-3]  159.93 162.08 270 bottom
FD1  FIDUCIAL  [FIDUCIAL_C40M80]  280.68 166.08 90 top
FD2  FIDUCIAL  [FIDUCIAL_C40M80]  52.27 7.53 0 top
FD3  FIDUCIAL  [FIDUCIAL_C40M80]  9.66 1.91 180 bottom
FD4  FIDUCIAL  [FIDUCIAL_C40M80]  284.72 152.18 180 bottom
FD5  FIDUCIAL  [FIDUCIAL_C40M80]  332.96 5.32 0 top
FD6  FIDUCIAL  [FIDUCIAL_C40M80]  332.96 5.32 180 bottom
FV2  1.1A_6V_SPR-P110  [F_SPR-P110]  238.77 163.33 90 bottom
FV3  1.1A_6V_SPR-P110  [F_SPR-P110]  223.93 166.97 180 bottom
H1  -  [H_3P8]  160.17 155.6 0 top
H2  -  [H_3P8]  122.67 90.9 0 top
H3  -  [H_3P6]  181.67 90.3 0 top
H4  -  [H_3P8]  205.07 48.5 0 top
H5  -  [H_3P8]  276.07 43.5 0 top
H6  -  [H_3P0]  179.67 6.5 0 top
H7  -  [H_3P8]  269.07 150.5 0 top
H8  -  [H_3P0]  5.07 69.8 0 top
H9  -  [H_3P0]  6.57 50.8 0 top
H10  -  [H_3P0]  28.07 54 0 top
H11  -  [H_3P6]  22.07 11.5 0 top
H12  -  [H_3P0]  276.17 170.6 0 top
H13  -  [H_3P6X4P2]  199.57 152 0 top
H14  -  [H_3P0]  202.22 180.1 0 top
H15  -  [H_3P0]  183.22 180.1 0 top
H16  -  [H_3P0]  22.07 4.2 0 top
H17  -  [H_3P0]  144.57 171.5 0 top
H18  -  [H_3P0]  102.07 6.5 0 top
H19  -  [H_3P0]  92.87 56.9 0 top
H20  -  [H_3P0]  297.87 76.25 0 top
H21  -  [H_3P0]  262.07 6.5 0 top
H22  -  [H_3P0]  197.87 55.6 0 top
H23  -  [H_4P1X3P6]  267.97 6.5 0 top
J1  -  [JUMP_43X79]  207 80.32 180 bottom
J4  -  [JUMP_43X79]  59.32 12.51 90 bottom
J5  -  [JUMP_43X79]  69.98 12.25 180 bottom
J6  -  [JUMP_43X79]  204.34 63.06 180 top
JACK1  YUQIU_PJ741-F07J1BE-C  [YUQIU_PJ741-F07J1BE-C_6P-T]  13.47 4.3 90 bottom
JACK2  YUQIU_PJ741-F07J1BE-C  [YUQIU_PJ741-F07J1BE-C_6P-T]  13.47 17 90 bottom
JCDRA  TE_2260531-1  [TE_2260531-1_46P-T]  151.87 177.71 0 bottom
JDIMM1  DEREN_40-42271-26001RHF  [DEREN_40-42271-26001RHF_260P-T]  111.69 60 0 bottom
JDIMM2  DEREN_40-42261-26001RHF  [DEREN_40-42261-26001RHF_260P-T]  111.69 47.2 180 bottom
JDP  ACON_MAR2F-20K1800  [ACON_MAR2F-20K1800_20P]  232.37 173.69 180 bottom
JEC  ACES_50521-0084N-P01  [ACES_50521-0084N-P01_8P]  284.31 8.44 270 bottom
JEDP  ACES_50473-0400M-P01  [ACES_50473-0400M-P01_40P]  151.62 180.27 0 top
JELC  AMPHE_G846A06201EU  [AMPHE_G846A06201EU_6P-T]  303.25 10.66 0 bottom
JFAN1  ACES_50278-00401-001  [ACES_50278-00401-001_4P]  106.87 63.25 180 top
JFAN2  ACES_50278-00401-001  [ACES_50278-00401-001_4P]  290.87 77.25 180 top
JHDD  STARC_111H30-000000-G4-R  [STARC_111H30-000000-G4-R_30P]  113.42 9.95 0 bottom
JHDMI  ACON_HMRA3-AK1L0C  [ACON_HMRA3-AK1L0C_19P]  212.12 174.3 0 bottom
JIO  ACES_50473-0300M-P01  [ACES_50473-0300M-P01_30P]  325.55 9.85 90 top
JKB  ACES_50552-03001-P01  [ACES_50552-03001-P01_30P]  223.47 7.75 180 bottom
JKB2  -  [ACES_50611-0100N-001_10P]  139.38 8.68 0 bottom
JKB3  ACES_87153-06411  [ACES_87153-06411_6P]  64.93 4.93 180 bottom
JKBBL  ACES_50552-02001-P01  [ACES_50552-02001-P01_20P]  169.82 7.75 180 bottom
JLAN  SANTA_130456-512  [SANTA_130456-512_13P]  249.64 171.77 0 bottom
JLOGO  ACES_87212-1600L  [ACES_87212-1600L_16P]  221.92 166.19 0 top
JP1  PAD-OPEN 43X39  [JUMP_43X39]  197.87 42.53 270 top
JP2  PAD-OPEN 43X39  [JUMP_43X39]  203.27 42.53 270 top
JP3  -  [JUMP_43X118]  130.61 9.24 180 top
JPCMC  INTEL_CMC_PRIMARY  [INTEL_CMC_PRIMARY_36P-T]  122.87 157.33 270 top
JPWR  ACES_87153-06411  [ACES_87153-06411_6P]  210.32 166.12 0 top
JRTC1  ACES_50271-00201-001  [ACES_50271-00201-001_2P]  292.69 37.1 180 bottom
JSPK  ACES_50278-00601-001  [ACES_50278-00601-001_6P-T]  52.18 14.22 180 bottom
JSSD1  LCN_DAN05-67406-0103  [LCN_DAN05-67406-0103_75P-T]  325.85 48.11 270 bottom
JSSD2  LCN_DAN05-67406-0103  [LCN_DAN05-67406-0103_75P-T]  271.85 24.25 270 bottom
JSSD3  LCN_DAN05-67406-0103  [LCN_DAN05-67406-0103_75P-T]  254.02 12.92 180 bottom
JTOBII  ACES_50450-0067N-P01  [ACES_50450-0067N-P01_6P]  154.56 165.75 0 top
JTP  ACES_51522-01601-P01  [ACES_51522-01601-P01_16P]  196.82 11.1 180 bottom
JTRONL  ACES_50450-0127N-001  [ACES_50450-0127N-001_12P]  43.47 49.15 180 bottom
JTRONR  ACES_50450-0127N-001  [ACES_50450-0127N-001_12P]  274.77 30.6 0 bottom
JUSB1  SDAN_608015-010232  [SDAN_608015-010232_10P]  16.55 41.4 90 bottom
JUSBC1  -  [JAE_DX07S024JJ5_24P-T]  190.1 178 0 bottom
JUSBC2  -  [JAE_DX07S024JJ5_24P-T]  7.55 62.92 270 top
JWDB  ACES_88266-04001  [ACES_50207-00471-P01_4P-T]  205.49 10.42 0 top
JWLAN  LCN_DAN05-67306-0102  [LCN_DAN05-67306-0102_67P]  300.32 33.57 0 bottom
LA3  BLM15AG121SN1D_L0402_2P  [MURAT_BLM15AG121SN1D_L0402_2P]  33.82 21.81 0 bottom
LA4  BLM15AG121SN1D_L0402_2P  [MURAT_BLM15AG121SN1D_L0402_2P]  30.83 21.76 0 bottom
LA5  BLM15AG121SN1D_L0402_2P  [MURAT_BLM15AG121SN1D_L0402_2P]  40.59 30.98 90 top
LA6  BLM15BB221SN1D_2P  [MURAT_BLM15BB221SN1D_2P]  34.53 35.77 180 bottom
LA7  BLM15PX330SN1D 0402  [MURAT_BLM15BD601SN1D_2P]  26.93 18.76 180 bottom
LA8  BLM15PX330SN1D 0402  [MURAT_BLM15BD601SN1D_2P]  27.76 20.92 0 top
LA9  FBMA-L11-160808-800LMT_2P  [KC_FBMA-L10-160808-800LMT_2P]  24.52 18.56 270 bottom
LA10  FBMA-L11-160808-800LMT_2P  [KC_FBMA-L10-160808-800LMT_2P]  17.45 21.55 90 bottom
LA11  BLM15PX330SN1D 0402  [MURAT_BLM15BD601SN1D_2P]  22.21 22.35 0 top
LA12  BLM15PX330SN1D 0402  [MURAT_BLM15BD601SN1D_2P]  21.93 23.9 0 top
LA50  BLM15PX121SN1D_2P  [MURAT_BLM15PX121SN1D_2P]  37.21 4.1 270 top
LA51  BLM15PX121SN1D_2P  [MURAT_BLM15PX121SN1D_2P]  36.71 3.21 180 bottom
LA52  BLM15PX121SN1D_2P  [MURAT_BLM15PX121SN1D_2P]  32.51 3.08 270 top
LA53  BLM15PX121SN1D_2P  [MURAT_BLM15PX121SN1D_2P]  30.99 4.41 180 top
LE1  FBMA-L11-160808-800LMT_0603  [KC_FBMA-L11-160808-800LMT_2P]  289.1 25.74 180 top
LE2  FBMA-L11-160808-800LMT_0603  [KC_FBMA-L11-160808-800LMT_2P]  286.41 9.87 0 top
LE3  MCM1012B900F06BP_4P  [INPAQ_MCM1012B900F06BP_4P-NPM]  158.18 162.91 180 top
LG1  BLM15BD121SN1D_0402  [R_0402]  231.92 79.66 180 top
LL1  BLM15AG121SN1D_L0402_2P  [MURAT_BLM15AG121SN1D_L0402_2P]  260.74 162.87 90 top
LM1  MCM1012B900F06BP_4P  [INPAQ_MCM1012B900F06BP_4P]  168.47 173.27 90 bottom
LT1  0.6UH_MND-04ABIR60M-XGL_20%  [MAG_MND-04ABIR60M-XGL_2P]  171.4 167.96 90 bottom
LT2  MCM1012B900F06BP_4P  [INPAQ_MCM1012B900F06BP_4P]  192.27 170.89 90 bottom
LT3  MCM1012B900F06BP_4P  [INPAQ_MCM1012B900F06BP_4P]  193.85 170.89 90 bottom
LU3  MCM1012B900F06BP_4P  [INPAQ_MCM1012B900F06BP_4P]  23.25 40.85 270 bottom
LU4  HCM1012GD670A05P  [INPAQ_MCM1012B900F06BP_4P]  22.9 39 180 top
LU5  HCM1012GD670A05P  [INPAQ_MCM1012B900F06BP_4P]  22.9 37.48 180 top
LU7  HCM1012GD670A05P  [INPAQ_MCM1012B900F06BP_4P]  13.34 62.25 180 top
LU8  HCM1012GD670A05P  [INPAQ_MCM1012B900F06BP_4P]  13.34 63.84 180 top
LU9  MCM1012B900F06BP_4P  [INPAQ_MCM1012B900F06BP_4P]  16.16 58.02 90 bottom
LU10  HCM1012GD670A05P  [INPAQ_MCM1012B900F06BP_4P]  13.47 57.82 180 top
LU11  HCM1012GD670A05P  [INPAQ_MCM1012B900F06BP_4P]  13.47 59.28 180 top
LV2  MCM1012B900F06BP_4P  [INPAQ_MCM1012B900F06BP_4P]  167.53 161.4 90 top
LV3  HCM1012GH900BP_4P  [INPAQ_HCM1012GH900BP_4P-NPM]  215.78 165.41 90 bottom
LV4  HCM1012GH900BP_4P  [INPAQ_HCM1012GH900BP_4P-NPM]  211.02 165.41 90 bottom
LV5  HCM1012GH900BP_4P  [INPAQ_HCM1012GH900BP_4P-NPM]  213.43 165.47 90 bottom
LV6  HCM1012GH900BP_4P  [INPAQ_HCM1012GH900BP_4P-NPM]  217.99 165.45 90 bottom
NOREF  -  []  111.64 228.27 0 top
NOREF#2  -  []  202.22 180.15 0 top
NOREF#3  -  []  145.08 30.78 0 top
NOREF#4  -  []  197.87 55.6 0 top
NOREF#5  -  []  115.69 22.83 0 top
NOREF#6  -  []  121.33 73.01 0 top
NOREF#7  -  []  276.17 170.6 0 top
NOREF#8  -  []  179.67 6.5 0 top
NOREF#9  -  []  199.57 152 0 top
NOREF#10  -  []  205.07 48.5 0 top
NOREF#11  -  []  88.92 11.44 0 top
NOREF#12  -  []  122.67 90.9 0 top
NOREF#13  -  []  102.07 6.5 0 top
NOREF#14  -  []  92.87 56.9 0 top
NOREF#15  -  []  161.13 16.36 0 top
NOREF#16  -  []  5.32 69.7 0 top
NOREF#17  -  []  183.22 180.15 0 top
NOREF#18  -  []  234.23 46.38 0 top
NOREF#19  -  []  28.07 54 0 top
NOREF#20  -  []  269.07 150.5 0 top
NOREF#21  -  []  160.17 155.6 0 top
NOREF#22  -  []  152.18 17.89 90 top
NOREF#23  -  []  297.87 76.25 0 top
NOREF#24  -  []  5.32 50.9 0 top
NOREF#25  -  []  181.67 90.3 0 top
NOREF#26  -  []  150.75 -28.39 0 top
NOREF#27  -  []  144.57 171.5 0 top
NOREF#28  -  []  276.07 43.5 0 top
NOREF#29  -  []  157.23 14.57 180 bottom
NOREF#30  -  []  166.8 34.86 180 bottom
PBATT1  ACES_50290-01201-P01  [ACES_50290-01201-P01_12P-T]  91.82 13.95 180 bottom
PC1  1000P_0402_50V7K  [C_0402]  84.1 37.75 90 bottom
PC2  100P_0402_50V8J  [C_0402]  85.2 37.72 90 bottom
PC3  1000P_0402_50V7K  [C_0402]  75.6 32.68 270 bottom
PC4  100P_0402_50V8J  [C_0402]  74.71 32.68 270 bottom
PC6  0.022U_0402_25V7K  [C_0402]  88.4 26.77 90 bottom
PC7  0.01UF_0402_25V7K  [C_0402]  87.51 26.77 90 bottom
PC8  1000P_0402_50V7K  [C_0402]  83.08 20.21 180 top
PC9  100P_0402_50V8J  [C_0402]  83.07 19.27 180 top
PC10  0.22U_0603_25V7K  [C_0603]  73.8 9.3 180 top
PC11  0.1U_0402_25V6  [C_0402]  67 13.61 90 top
PC12  .1U_0402_16V7K  [C_0402]  68.88 8.19 270 top
PC13  .1U_0402_16V7K  [C_0402]  293.21 6.32 270 top
PC14  1U_0603_25V6K  [C_0603]  82.41 7.82 180 top
PC100  0.1U_0402_25V6  [C_0402]  45.99 40.97 180 top
PC101  4.7U_0603_6.3V6K  [C_0603]  53.95 48.56 90 bottom
PC102  22U_0805_25V6M  [C_0805]  52.4 33.81 180 top
PC103  2200P_0402_50V7K  [C_0402]  46 41.86 180 top
PC104  22U_0805_25V6M  [C_0805]  48.27 38.73 270 top
PC105  0.1U_0402_25V6  [C_0402]  57.53 45.75 0 bottom
PC106  0.1U_0402_25V6  [C_0402]  49.2 45.61 0 bottom
PC108  220U_D2_6.3VY_R15M  [C_D2]  37.69 39.91 180 bottom
PC109  680P_0603_50V8J  [C_0603]  43.76 30.89 0 top
PC110  680P_0603_50V8J  [C_0603]  44.08 32.11 0 top
PC111  4.7U_0603_6.3V6K  [C_0603]  53.73 42.32 0 bottom
PC112  4.7U_0603_6.3V6K  [C_0603]  61.65 47.28 0 top
PC113  22U_0805_25V6M  [C_0805]  50.05 38.73 270 top
PC114  22U_0805_25V6M  [C_0805]  52.39 35.58 180 top
PC115  220U_D2_6.3VY_R15M  [C_D2]  37.69 44.67 180 bottom
PC116  220U_D2_6.3VY_R15M  [C_D2]  42.3 18.76 180 bottom
PC117  220U_D2_6.3VY_R15M  [C_D2]  41.86 23.21 90 bottom
PC118  1U_0402_25V6K  [C_0402]  53.94 31.91 270 top
PC119  1000P_0402_50V7K  [C_0402]  54.87 31.92 270 top
PC200  0.1U_0402_25V6  [C_0402]  92.71 33.38 0 top
PC201  2200P_0402_50V7K  [C_0402]  92.71 34.27 0 top
PC202  10U_0805_25V6K~D  [C_0805]  92.85 32.33 270 top
PC203  10U_0805_25V6K~D  [C_0805]  91.07 32.37 270 top
PC204  0.1U_0603_25V7K  [C_0603]  88.21 42.01 0 bottom
PC205  10U_0805_6.3V6K  [C_0805]  91.41 47.53 180 bottom
PC206  10U_0805_6.3V6K  [C_0805]  91.41 49.37 180 bottom
PC207  1U_0603_10V6K  [C_0603]  93.61 39.4 90 bottom
PC208  1U_0402_25V6K  [C_0402]  88.64 35.15 90 top
PC209  220U_D2 SX_2VY_R9M  [C_D2]  96.27 29.05 270 bottom
PC210  0.033U_0402_16V7K  [C_0402]  92.91 47.14 90 bottom
PC211  680P_0402_50V7K  [C_0402]  97.27 34.28 180 top
PC212  1U_0603_10V6K  [C_0603]  94.94 40.8 270 bottom
PC213  0.1U_0402_10V7K  [C_0402]  95.88 44.55 0 bottom
PC214  0.1U_0402_10V7K  [C_0402]  95.88 45.43 0 bottom
PC215  220U_D2 SX_2VY_R9M  [C_D2]  91.41 29.14 270 bottom
PC216  1000P_0402_50V7K  [C_0402]  87.72 35.15 90 top
PC217  0.1U_0402_25V6  [C_0402]  103.37 52.27 270 top
PC218  0.1U_0402_25V6  [C_0402]  104.24 54.44 90 top
PC300  0.1U_0402_16V7K  [C_0402]  248.1 18.08 270 top
PC301  0.1U_0402_25V6  [C_0402]  259.22 26.71 270 bottom
PC302  2200P_0402_50V7K  [C_0402]  257.22 23.2 270 top
PC303  10U_0805_25V6K~D  [C_0805]  256.96 24.45 180 top
PC304  10U_0805_25V6K~D  [C_0805]  256.93 26.98 270 bottom
PC305  0.1U_0603_25V7K  [C_0603]  246.58 24.99 0 top
PC306  220U_D2 SX_2VY_R9M  [C_D2]  245.93 32.58 270 bottom
PC307  220U_D2 SX_2VY_R9M  [C_D2]  241.04 32.58 270 bottom
PC308  1U_0603_6.3V6M  [C_0603]  249.12 24.16 90 top
PC309  680P_0402_50V7K  [C_0402]  255.85 23.98 270 bottom
PC310  1U_0402_25V6K  [C_0402]  258.26 26.71 270 bottom
PC311  1000P_0402_50V7K  [C_0402]  256.33 23.18 270 top
PC500  330P_0402_50V7K  [C_0402]  124.26 138.48 180 top
PC501  47P_0402_50V8J~D  [C_0402]  124.06 133.79 270 bottom
PC502  0.1U_0402_25V6  [C_0402]  124.05 132.87 90 top
PC503  1U_0402_16V6K  [C_0402]  126.54 137.58 90 top
PC504  0.22U_0603_25V7K  [C_0603]  127.64 137.64 90 top
PC505  68P_0402_50V8J  [C_0402]  124.79 139.8 180 top
PC506  6800P_0402_25V7K  [C_0402]  123.9 141.57 270 top
PC507  1000P_0402_50V7K  [C_0402]  119.55 137.03 270 bottom
PC508  470P_0402_50V7K  [C_0402]  121.34 137.02 180 bottom
PC509  2200P_0402_50V7K  [C_0402]  132.15 137.56 90 bottom
PC510  0.01UF_0402_25V7K  [C_0402]  133.09 141.12 180 bottom
PC511  .1U_0402_16V7K  [C_0402]  129.61 135.72 90 top
PC512  0.022U_0402_25V7K  [C_0402]  133.09 140.24 180 bottom
PC513  0.01UF_0402_25V7K  [C_0402]  121.67 140.05 180 top
PC514  1500P_0402_50V7K  [C_0402]  134.03 143.89 270 bottom
PC515  0.01UF_0402_25V7K  [C_0402]  129.74 139.8 270 top
PC516  0.15U_0402_16V7K  [C_0402]  121.34 140.95 180 bottom
PC517  0.068U_0402_16V7K  [C_0402]  121.34 141.84 180 bottom
PC518  2200P_0402_50V7K  [C_0402]  121.29 143.62 270 bottom
PC519  330P_0402_50V7K  [C_0402]  129.37 144.62 180 top
PC520  68P_0402_50V8J  [C_0402]  127.63 141.89 0 top
PC521  2200P_0402_50V7K  [C_0402]  128.53 140.24 180 top
PC522  330P_0402_50V7K  [C_0402]  133.09 145.65 180 bottom
PC523  .1U_0402_16V7K  [C_0402]  118.63 143.87 270 bottom
PC524  0.022U_0402_25V7K  [C_0402]  130.03 146.02 90 bottom
PC525  0.022U_0402_25V7K  [C_0402]  121.61 145.52 270 bottom
PC526  0.022U_0402_25V7K  [C_0402]  128.19 145.96 90 top
PC527  0.022U_0402_25V7K  [C_0402]  127.3 145.96 90 top
PC528  0.022U_0402_25V7K  [C_0402]  119.69 144.75 0 bottom
PC529  .1U_0402_16V7K  [C_0402]  129.98 147.86 0 bottom
PC530  0.033U_0402_16V7K  [C_0402]  125.27 146.94 270 top
PC531  0.22U_0402_16V7K  [C_0402]  126.15 146.94 270 top
PC532  2200P_0402_50V7K  [C_0402]  127.29 146.92 0 bottom
PC533  470P_0402_50V7K  [C_0402]  126.17 147.81 180 bottom
PC534  0.01UF_0402_25V7K  [C_0402]  126.69 144.62 0 top
PC535  330P_0402_50V7K  [C_0402]  123.91 142.59 90 top
PC536  68P_0402_50V8J  [C_0402]  125.1 143.48 270 top
PC537  680P_0402_50V7K  [C_0402]  123.5 147.81 180 bottom
PC538  6800P_0402_25V7K  [C_0402]  127.58 143.73 180 top
PC539  100U_25V_M  [C_ECST250ADA101MF611]  144.92 155 270 bottom
PC540  1U_0402_6.3V6K  [C_0402]  158.11 144.99 90 top
PC541  0.22U_0603_16V7K  [C_0603]  160.42 147.71 270 bottom
PC542  100U_25V_M  [C_ECST250ADA101MF611]  152.09 155 270 bottom
PC543  10U_0805_25V6K  [C_0805]  160.16 143.25 270 top
PC544  10U_0805_25V6K  [C_0805]  161.87 143.25 270 top
PC545  10U_0805_25V6K  [C_0805]  160.39 144.37 90 top
PC546  0.1U_0402_25V6  [C_0402]  163.21 141.89 0 top
PC547  2200P_0402_50V7K  [C_0402]  159.09 144.28 90 top
PC548  33P_0603_50V8J  [C_0603]  161.23 136.24 0 top
PC549  1U_0402_6.3V6K  [C_0402]  169.64 147.11 180 top
PC550  0.22U_0603_16V7K  [C_0603]  168.75 147.63 270 bottom
PC551  10U_0805_25V6K  [C_0805]  168.56 143.21 270 top
PC552  10U_0805_25V6K  [C_0805]  170.28 143.21 270 top
PC553  10U_0805_25V6K  [C_0805]  169.97 144.41 90 top
PC554  0.1U_0402_25V6  [C_0402]  171.29 144.43 90 top
PC555  2200P_0402_50V7K  [C_0402]  168.65 144.42 90 top
PC556  33P_0603_50V8J  [C_0603]  169.87 136.24 0 top
PC557  1U_0402_6.3V6K  [C_0402]  174.88 144.74 90 top
PC558  0.22U_0603_16V7K  [C_0603]  177.1 147.69 270 bottom
PC559  10U_0805_25V6K  [C_0805]  177.34 144.37 90 top
PC560  10U_0805_25V6K  [C_0805]  178.64 143.23 270 top
PC561  10U_0805_25V6K  [C_0805]  176.87 143.23 270 top
PC562  0.1U_0402_25V6  [C_0402]  178.65 144.22 90 top
PC563  2200P_0402_50V7K  [C_0402]  179.54 144.22 90 top
PC564  33P_0603_50V8J  [C_0603]  178.12 136.24 0 top
PC565  10U_0805_25V6K~D  [C_0805]  145.23 147.94 180 top
PC566  1U_0402_6.3V6K  [C_0402]  142.25 147.98 90 top
PC567  0.22U_0603_16V7K  [C_0603]  144.41 150.95 270 bottom
PC568  10U_0805_25V6K~D  [C_0805]  144.09 146.5 270 top
PC569  10U_0805_25V6K~D  [C_0805]  145.81 146.5 270 top
PC570  680P_0603_50V7K  [C_0603]  145.29 139.42 0 top
PC571  0.1U_0402_25V6  [C_0402]  147.09 147.54 90 top
PC572  2200P_0402_50V7K  [C_0402]  146.22 147.56 90 top
PC573  1U_0402_6.3V6K  [C_0402]  150.56 147.98 90 top
PC574  0.22U_0603_16V7K  [C_0603]  152.74 150.98 270 bottom
PC575  10U_0805_25V6K~D  [C_0805]  152.55 146.52 270 top
PC576  10U_0805_25V6K~D  [C_0805]  154.31 146.52 270 top
PC577  10U_0805_25V6K~D  [C_0805]  153.49 147.95 180 top
PC578  0.1U_0402_25V6  [C_0402]  154.48 147.5 90 top
PC579  2200P_0402_50V7K  [C_0402]  155.35 147.5 90 top
PC580  680P_0603_50V7K  [C_0603]  153.87 139.42 0 top
PC581  2200P_0402_50V7K  [C_0402]  186.94 139.11 270 top
PC582  0.1U_0402_25V6  [C_0402]  187.82 139.11 270 top
PC583  10U_0805_25V6K  [C_0805]  183.04 139.19 270 top
PC584  10U_0805_25V6K  [C_0805]  184.75 139.18 270 top
PC585  10U_0805_25V6K  [C_0805]  184.94 143.61 180 top
PC586  0.22U_0603_16V7K  [C_0603]  184.19 146.22 270 bottom
PC587  680P_0603_50V7K  [C_0603]  183.14 134.46 90 top
PC588  4.7U_0402_6.3V6M  [C_0402]  182.06 142.64 90 top
PC589  2200P_0402_50V7K  [C_0402]  118.7 117.95 180 bottom
PC590  0.22U_0402_10V6K  [C_0402]  124.52 118.21 0 bottom
PC591  680P_0603_50V7K  [C_0603]  118.44 108.11 270 bottom
PC592  10U_0805_25V6K  [C_0805]  120.51 120.3 0 bottom
PC593  0.1U_0603_25V7K  [C_0603]  119.39 113.26 0 bottom
PC594  0.1U_0402_25V6  [C_0402]  118.7 117.06 180 bottom
PC596  22U_0603_6.3V6M  [C_0603]  121.61 104.75 180 bottom
PC597  22U_0603_6.3V6M  [C_0603]  121.61 106.08 180 bottom
PC598  22U_0603_6.3V6M  [C_0603]  124.08 106.08 0 bottom
PC599  22U_0603_6.3V6M  [C_0603]  124.08 104.75 0 bottom
PC701  0.1U_0402_25V6  [C_0402]  58.05 28.67 180 top
PC702  0.047U_0402_25V7K  [C_0402]  61.78 23.21 0 top
PC703  0.1U_0402_25V6  [C_0402]  64.33 27.21 270 top
PC704  2200P_0402_50V7K  [C_0402]  63.45 27.21 270 top
PC705  10U_0805_25V6K~D  [C_0805]  65.73 27.08 270 top
PC706  10U_0805_25V6K~D  [C_0805]  67.51 27.08 270 top
PC707  0.1U_0603_25V7K  [C_0603]  58.37 22.61 90 bottom
PC708  0.1U_0402_25V6  [C_0402]  58.48 25.75 0 bottom
PC709  0.01UF_0402_25V7K  [C_0402]  59.64 24.56 270 bottom
PC710  2.2U_0603_16V6K  [C_0603]  59.23 21.37 180 bottom
PC711  1U_0603_25V6K  [C_0603]  59.44 22.64 0 bottom
PC712  22U_0805_25V6M  [C_0805]  82.47 26.91 90 bottom
PC713  22U_0805_25V6M  [C_0805]  84.18 26.91 90 bottom
PC714  22U_0805_25V6M  [C_0805]  86.03 26.94 90 bottom
PC715  680P_0402_50V7K  [C_0402]  63.76 21.04 90 top
PC716  0.1U_0402_25V6  [C_0402]  57.46 15.91 0 top
PC717  0.1U_0402_25V6  [C_0402]  58.38 16.8 180 top
PC718  100P_0402_50V8J  [C_0402]  52.96 24.69 0 top
PC719  0.01UF_0402_25V7K  [C_0402]  56.34 24.86 270 bottom
PC720  100P_0402_50V8J  [C_0402]  52.97 23.8 0 top
PC721  0.1U_0402_25V6  [C_0402]  56.59 16.81 270 top
PC722  1000P_0402_50V7K  [C_0402]  70.13 40.58 180 top
PC723  1000P_0402_50V7K  [C_0402]  69.92 33.37 180 top
PC724  0.1U_0402_25V6  [C_0402]  118.65 78.77 180 top
PC725  0.022U_0603_25V7K  [C_0603]  79.93 28.33 90 top
PC726  1000P_0402_50V7K  [C_0402]  62.56 27.22 270 top
PC727  1U_0402_25V6K  [C_0402]  61.67 27.22 270 top
PC800  10U_0805_25V6K~D  [C_0805]  198.29 76.23 270 top
PC801  0.22U_0402_16V7K  [C_0402]  196.96 73.72 90 top
PC802  680P_0402_50V7K  [C_0402]  198.87 78.58 270 top
PC803  2.2U_0402_16V6K  [C_0402]  195.33 77.76 0 top
PC804  22U_0603_6.3V6M  [C_0603]  196.99 87.49 180 bottom
PC805  22U_0603_6.3V6M  [C_0603]  198.26 82.25 0 bottom
PC806  680P_0402_50V7K  [C_0402]  231.83 35.78 0 bottom
PC807  1U_0603_6.3V6M  [C_0603]  195.33 76.67 0 top
PC808  0.1U_0603_25V7K  [C_0603]  198.34 79.85 270 bottom
PC809  330P_0402_50V7K  [C_0402]  193.04 77.49 0 bottom
PC810  10U_0603_6.3V6M  [C_0603]  238.32 36.42 90 bottom
PC811  0.1U_0402_16V7K  [C_0402]  233.08 40.24 90 bottom
PC812  22U_0603_6.3V6M  [C_0603]  228.42 36.67 270 bottom
